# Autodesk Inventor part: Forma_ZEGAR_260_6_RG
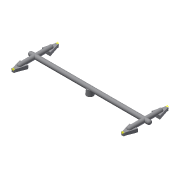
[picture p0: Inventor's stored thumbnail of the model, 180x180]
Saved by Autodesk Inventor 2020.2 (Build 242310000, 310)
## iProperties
Created: 2015-01
Part Number: Forma_ZEGAR_260_6_RG
Material: Ogólny
Document SubType Name: Modeling
Designer: F.Stasiak
Density: 1 g/cm^3
Appearance: Domyślna
Catalog Web Link: www.expertbooks.pl
Manager: www.cadconsulting.pl
Company: Fabian Stasiak CAD Consulting
Author: F.Stasiak
Subject: Zbiór ćwiczeń. Autodesk Inventor 2020. Kurs Professional
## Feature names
1. Wyciągnięcie proste7 [Extrusion]
2. Przeciągnięcie1
3. Obrót1 [Revolution]
4. Wyciągnięcie proste1 [Extrusion]
5. Przeciągnięcie2
6. Obrót2 [Revolution]
7. Wyciągnięcie proste2 [Extrusion]
8. Przeciągnięcie3
9. Obrót3 [Revolution]
10. Wyciągnięcie proste3 [Extrusion]
11. Przeciągnięcie4
12. Obrót4 [Revolution]
13. Wyciągnięcie proste4 [Extrusion]
14. Przeciągnięcie5
15. Obrót5 [Revolution]
16. Wyciągnięcie proste5 [Extrusion]
17. Przeciągnięcie6
18. Obrót6 [Revolution]
19. Wyciągnięcie proste6 [Extrusion]
20. Wyciągnięcie złożone1
21. Wyciągnięcie złożone2
22. Wyciągnięcie złożone3
23. Wyciągnięcie złożone4
## Parameters: d0 = -9.8085 mm, d1 = 39 mm, d2 = 8 mm, d3 = 3 mm, d4 = 0, d5 = 0, d6 = -3 mm, d7 = 3 mm, d8 = 180 deg, d9 = 3 mm, d10 = 3 mm, d11 = 0, d12 = 3 mm, d13 = 0, d14 = 0, d15 = -3 mm, d16 = 3 mm, d17 = 180 deg, d18 = 3 mm, d19 = 3 mm, d20 = 0, d21 = 3 mm, d22 = 0, d23 = 0, d24 = 3 mm, d25 = 3 mm, d26 = 180 deg, d27 = 3 mm, d28 = 3 mm, d29 = 0, d30 = 3 mm, d31 = 0, d32 = 0, d33 = 3 mm, d34 = 3 mm, d35 = 180 deg, d36 = 3 mm, d37 = 3 mm, d38 = 0, d39 = 3 mm, d40 = 0, d41 = 0, d42 = 3 mm, d43 = 3 mm, d44 = 180 deg, d45 = 3 mm, d46 = 3 mm, d47 = 0, d48 = 3 mm, d49 = 0, d50 = 0, d51 = 3 mm, d52 = 3 mm, d53 = 180 deg, d54 = 3 mm, d55 = 3 mm, d56 = 0, d58 = 2 mm, d59 = 2 mm, d60 = 87 deg, d61 = 87 deg, d62 = 6 mm, d63 = 2.5 mm, d64 = 87 deg, d65 = 87 deg, d66 = 0, d67 = 90 deg, d68 = 0, d69 = 90 deg, d70 = 1 mm, d72 = 2 mm, d73 = 2 mm, d74 = 87 deg, d75 = 87 deg, d76 = 6 mm, d77 = 2.5 mm, d78 = 87 deg, d79 = 87 deg, d80 = 0, d81 = 90 deg, d82 = 0, d83 = 90 deg, d84 = 1 mm, d86 = 2 mm, d87 = 2 mm, d88 = 87 deg, d89 = 87 deg, d90 = 6 mm, d91 = 2.5 mm, d92 = 87 deg, d93 = 87 deg, d94 = 0, d95 = 90 deg, d96 = 0, d97 = 90 deg, d98 = 1 mm, d100 = 2 mm, d101 = 2 mm, d102 = 87 deg, d103 = 87 deg, d104 = 6 mm, d105 = 2.5 mm, d106 = 87 deg, d107 = 87 deg, d108 = 0, d109 = 90 deg, d110 = 0, d111 = 90 deg, d112 = 1 mm, d113 = 4 mm, d114 = 5 deg, d115 = 1 mm, d116 = 1 mm, d117 = 1 mm, d118 = 1 mm
